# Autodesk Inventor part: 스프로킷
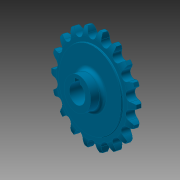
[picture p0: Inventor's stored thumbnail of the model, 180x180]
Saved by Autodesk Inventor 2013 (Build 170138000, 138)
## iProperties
Created: 2016-03
Part Number: 스프로킷
Material: 강철, 탄소
Document SubType Name: Modeling
Designer: mduedu
Density: 7.87 g/cm^3
Mass: 301.818 g
Surface Area: 124.882 cm^2
Volume: 38.3505 cm^3
Author: mduedu
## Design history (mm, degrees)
sketch "스케치1"
  geometry: L1 (0, 5)-(29.5, 5); L2 (29.5, 5)-(29.5, 4.1); L3 (30, 3.6)-(33.625, 3.6); L4 (40, 2)-(40, 0); L5 (40, 0)-(0, 0); L6 (0, 0)-(0, 5); L7 (0, -5)-(29.5, -5); L8 (29.5, -5)-(29.5, -4.1); L9 (30, -3.6)-(33.625, -3.6); L10 (40, -2)-(40, 0); L11 (0, 0)-(0, -5); A1 r 13.5 centre (33.625, -9.9) between (40, 2) and (33.625, 3.6); A2 r 13.5 centre (33.625, 9.9) between (33.625, -3.6) and (40, -2); A3 r 0.5 centre (30, 4.1) between (29.5, 4.1) and (30, 3.6); A4 r 0.5 centre (30, -4.1) between (30, -3.6) and (29.5, -4.1); 2 further points
  constraints: 22 end point, 8 point on circle, 6 symmetric about line, 5 tangent, 4 centre point, 4 parallel, 4 point on line, 1 equal radius, 1 horizontal, 1 perpendicular, 1 other
  dimensions: "d0" = 80 diameter of L4 L6; "d2" = 59 diameter of L2 L6; "d3" = 1.6 vertical distance of L4.start L3.end; "d4" = 3.6 distance from line of L4.end L3; "d5" = 5 distance between parallel lines of L5 L1; "d6" = 13.5 radius of A1; "d15" = 0.5 radius of A3
revolve "회전1" sketch "스케치1" stored, may be unused: angle "d7" = 90 deg
sketch "스케치2" dims "d8" = 65.2, "d11" = 80
  geometry: L1 (0, 0)-(0, 32.6); A1 r 36.57 centre (0, 0) between (-16.231, 32.771) and (0, 36.57); A2 r 3.97 centre (0, 36.57) between (-3.866, 35.665) and (0, 32.6); A3 r 12.7 centre (-16.231, 32.771) between (-3.866, 35.665) and (-5.534, 39.615); A4 r 12.7 centre (16.231, 32.771) between (5.534, 39.615) and (3.866, 35.665); A5 r 3.97 centre (0, 36.57) between (0, 32.6) and (3.866, 35.665); A6 r 40 centre (0, 0) between (5.534, 39.615) and (-5.534, 39.615); 2 further points
  constraints: 12 point on circle, 6 centre point, 4 coincident, 3 symmetric about line, 2 end point, 1 point on line, 1 tangent, 1 vertical, 1 vertical alignment, 7 other
  dimensions: "d10" = 73.14 diameter of A1; "d12" = 12.7 radius of A3
extrude "돌출1" cut sketch "스케치2" stored distance "d13" = 10; taper "d14" = 0 deg
sketch "스케치3"
  geometry: C1 r 12.5 at (0, 0); 1 further point
  constraints: 1 centre point, 1 coincident
  dimensions: "d19" = 25 diameter of C1
extrude "돌출2" join sketch "스케치3" distance "d20" = 10; taper "d21" = 0 deg
fillet "모깎기1" dims "d22" = 3
sketch "스케치4"
  geometry: L1 (-2.5, 0)-(2.5, 0); L2 (2.5, 0)-(2.5, 9.8); L3 (2.5, 9.8)-(-2.5, 9.8); L4 (-2.5, 9.8)-(-2.5, 0); C1 r 7.5 at (0, 0); 2 further points
  constraints: 8 end point, 2 coincident, 2 parallel, 1 centre point, 1 horizontal, 1 midpoint, 1 perpendicular
  dimensions: "d23" = 15 diameter of C1; "d25" = 5 distance of L2.end L3.end; "d26" = 9.8 distance of L1.end L2.end
extrude "돌출3" cut sketch "스케치4" stored distance "d27" = 8; taper "d28" = 0 deg
node "솔리드1"
pattern_circular "원형 패턴1" dims angle "d17" = 360 deg
